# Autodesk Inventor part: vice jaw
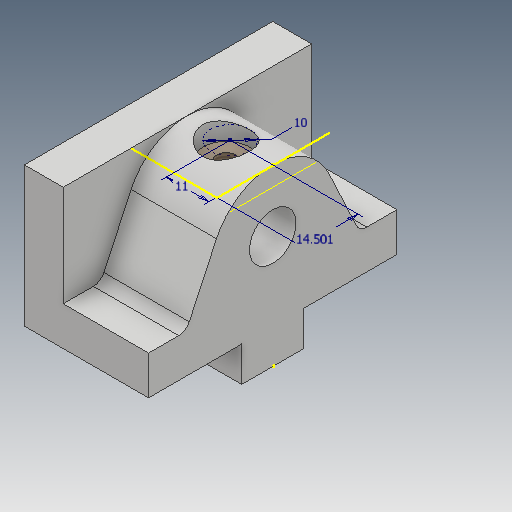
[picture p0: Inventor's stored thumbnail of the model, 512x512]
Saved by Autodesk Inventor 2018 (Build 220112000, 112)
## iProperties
Created: 2016-03
Part Number: vice jaw
Material: Generic
Document SubType Name: Modeling
Designer: Sandeep
Density: 1 g/cm^3
Appearance: Default
Mass: 55.5986 g
Surface Area: 129.526 cm^2
Volume: 55.5986 cm^3
Author: Sandeep
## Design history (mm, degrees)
sketch "Sketch1"
  geometry: L1 (0, 0)-(-32, 0); L2 (-32, 0)-(-32, 36); L3 (-32, 36)-(-22, 36); L4 (-22, 36)-(-22, 10); L5 (-22, 10)-(0, 10); L6 (0, 10)-(0, 0)
  constraints: 12 end point, 5 perpendicular, 1 horizontal
  dimensions: "d0" = 36 distance between parallel lines of L1 L3; "d1" = 32 distance of L1.start L1.end; "d2" = 10 distance of L5.end L1.start; "d3" = 10 distance of L2.end L3.end
extrude "Extrusion1" new body sketch "Sketch1" stored distance "d4" = 64; taper "d5" = 0 deg
sketch "Sketch2"
  geometry: L1 (64, 10)-(64, 0) reference; L2 (64, 10)-(64, 0); L3 (64, 0)-(54.317, 0); L4 (64, 0)-(0, 0) reference; L5 (54.317, 0)-(46.501, -16.762); L6 (0, 0)-(0, 10); L7 (0, 10)-(64, 10); L8 (64, -26)-(0, -26) reference; L9 (0, 0)-(9.683, 0); L10 (32, 10)-(32, -39.451); L11 (9.683, 0)-(17.499, -16.762); A1 r 16 centre (32, -10) between (17.499, -16.762) and (46.501, -16.762); 1 further point
  constraints: 16 end point, 3 point on line, 2 collinear, 2 perpendicular, 2 point on circle, 2 symmetric about line, 2 tangent, 1 centre point, 1 coincident, 1 vertical
  dimensions: "d8" = 16 radius of A1; "d9" = 50 deg angle of L11 L5
extrude "Extrusion2" join sketch "Sketch2" stored distance "d10" = 32; taper "d11" = 0 deg
fillet "Fillet1" dims "d12" = 3
sketch "Sketch3"
  geometry: L1 (40, 0)-(40, 9); L2 (40, 9)-(24, 9); L3 (24, 9)-(24, 0); L4 (24, 0)-(40, 0); L5 (0, 0)-(64, 0) reference; L6 (32, 0)-(32, -54.171)
  constraints: 10 end point, 2 perpendicular, 2 vertical, 1 collinear, 1 point on line, 1 other
  dimensions: "d13" = 16 distance between parallel lines of L3 L1; "d14" = 9 distance of L2.end L3.end
extrude "Extrusion3" join sketch "Sketch3" stored distance "d15" = 32; taper "d16" = 0 deg
sketch "Sketch4"
  geometry: L1 (-24, 19)-(-40, 19) reference; L2 (-32, 19)-(-32, -29.453); C1 r 6 at (-32, -10); A1 r 16 centre (-32, -10) between (-46.501, -16.762) and (-17.499, -16.762) reference; 1 further point
  constraints: 2 end point, 1 centre point, 1 concentric, 1 midpoint, 1 point on line, 1 vertical
  dimensions: "d17" = 12 diameter of C1
extrude "Extrusion4" cut sketch "Sketch4" distance "d18" = 24; taper "d19" = 0 deg
sketch "Sketch6"
  geometry: 1 further point
workplane "Work Plane1"
sketch "Sketch7"
  geometry: L1 (14.501, 0)-(-14.501, 0) reference; L2 (14.501, 0)-(14.501, -22) reference; C1 r 5 at (0, -11); 1 further point
  constraints: 1 centre point
  dimensions: "d22" = 10 diameter of C1; "d23" = 11 distance from line of L1 C1.centre; "d24" = 14.50092 distance from line of C1.centre L2
workplane "Work Plane2"
hole "Hole1" diameter "d37" = 4.917; stored, may be unused: countersink angle "d41" = 90 deg, drill point angle "d43" = 118 deg; dims "d35" = 8, "d36" = 8, "d38" = 12, "d39" = 4, "d40" = 2, "d42" = 16
hole "Hole2" diameter "d46" = 4.917; stored, may be unused: countersink angle "d50" = 90 deg, drill point angle "d52" = 118 deg; dims "d44" = 8, "d45" = 8, "d47" = 12, "d48" = 4, "d49" = 2, "d51" = 16
hole "Hole3" diameter "d55" = 4.917; stored, may be unused: countersink angle "d59" = 82 deg, drill point angle "d61" = 118 deg; dims "d53" = 20, "d54" = 32, "d56" = 12, "d57" = 12, "d58" = 5, "d60" = 17.1
sketch "Sketch10"
  geometry: 1 further point
body "Solid1"
